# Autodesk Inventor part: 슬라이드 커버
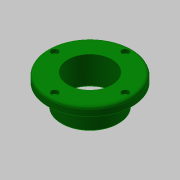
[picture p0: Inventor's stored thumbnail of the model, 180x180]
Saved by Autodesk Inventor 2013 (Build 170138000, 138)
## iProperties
Created: 2015-10
Part Number: 슬라이드 커버
Document SubType Name: Modeling
Designer: mdu
Density: 2.71 g/cm^3
Material: 알루미늄 6061
Mass: 218.252 g
Surface Area: 239.629 cm^2
Volume: 80.5358 cm^3
Author: mdu
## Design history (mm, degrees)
sketch "스케치1"
  geometry: C1 r 47.5 at (0, 0); C2 r 32.5 at (0, 0); 1 further point
  constraints: 2 centre point, 2 coincident
  dimensions: "d33" = 95 diameter of C1; "d35" = 65 diameter of C2
extrude "돌출1" new body sketch "스케치1" distance "d0" = 10; taper "d1" = 0 deg
extrude "돌출2" join sketch "스케치1" distance "d2" = 25; taper "d3" = 0 deg
hole "구멍1" diameter "d6" = 50; stored, may be unused: countersink angle "d10" = 90 deg, drill point angle "d12" = 118 deg; dims "d4" = 10, "d5" = 10, "d7" = 6, "d8" = 4, "d9" = 2, "d11" = 8
sketch "스케치2" dims "d36" = 80
  geometry: 4 further points
  constraints: 2 coincident, 2 vertical alignment, 2 other
hole "구멍2" sketch "스케치2" at (0, 40) diameter "d13" = 4.5; stored, may be unused: countersink angle "d17" = 90 deg, drill point angle "d19" = 118 deg; dims "d14" = 6, "d15" = 8, "d16" = 4.4, "d18" = 8
fillet "모깎기1" dims "d23" = 3
chamfer "모따기1" distance "d24" = 1; stored, may be unused: second distance "d25" = 2, angle "d26" = 45 deg
sketch "스케치3"
  geometry: C1 r 25 at (0, 0); C2 r 30 at (0, 0); C3 r 26 at (0, 0) reference; 1 further point
  constraints: 2 centre point, 2 coincident
  dimensions: "d27" = 60 diameter of C2
extrude "돌출3" cut sketch "스케치3" distance "d28" = 3; taper "d29" = 0 deg
chamfer "모따기2" distance "d30" = 1; stored, may be unused: second distance "d31" = 2, angle "d32" = 45 deg
node "솔리드1"
pattern_circular "원형 패턴1" dims angle "d21" = 360 deg
